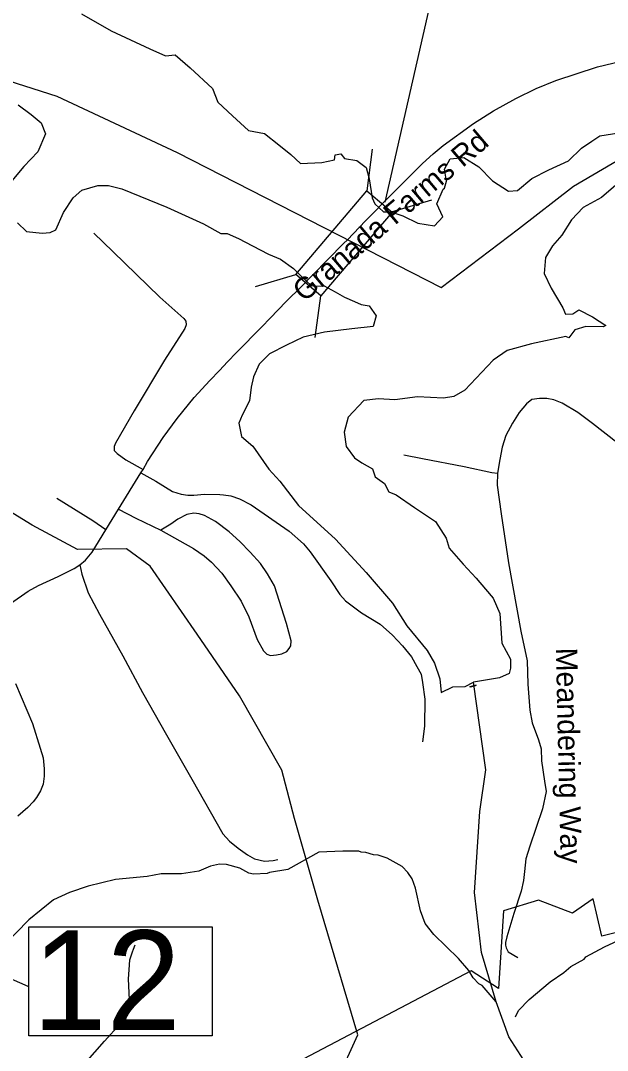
# Model space of a CAD drawing. Extents: x 1159738 to 1321356, y 736314 to 882035.
# Drawn here: x 1283504 to 1285565, y 753698 to 757313 of the extents above; entities that cross this region are included whole.
import ezdxf

# ---------------------------------------------------------------- set-up
doc = ezdxf.new("R2010")
doc.units = 0
for name, color, linetype in [('Exist Boundary Political City Limit New', 7, 'Continuous'), ('Exist Hydrographic Creek Double Shore', 7, 'Continuous'), ('Exist Hydrographic Creek Single Shore', 7, 'Continuous'), ('Exist Hydrographic Lake Dam', 7, 'Continuous'), ('Exist Hydrographic Misc Water Feature', 7, 'Continuous'), ('Exist Road Non-System Type 51', 7, 'Continuous'), ('Exist Road Non-System Type 51 Label', 7, 'Continuous'), ('Exist Road Secondary Structure Standard Bridge CELL', 7, 'Continuous'), ('Exist Road Secondary Structure Standard Bridge Number Label', 7, 'Continuous'), ('Exist Road Secondary Type 51 Attributed', 7, 'Continuous'), ('Exist Road Secondary Type 51 Label', 7, 'Continuous'), ('Exist Utilities Electrical Transmission Line', 7, 'Continuous'), ('Map Preparation Boundary City Limit Buffer Line', 7, 'Continuous')]:
    doc.layers.add(name, color=color, linetype=linetype)

msp = doc.modelspace()

# ---------------------------------------------------------------- linework, layer by layer
at = {"layer": 'Exist Boundary Political City Limit New'}
for points in [[(1280018.1, 757340.6), (1280236.8, 756834.3), (1280495.5, 756917.6), (1280706.6, 756441.3), (1280847.5, 756529.7), (1280868.5, 756454.3), (1280930.2, 756459.6), (1280976.3, 756484.6), (1280986.6, 756728.2), (1280999.3, 756824.5), (1281041.5, 756912.8), (1281181.8, 757003), (1281357.9, 756992.9), (1281622.7, 757052.4), (1281779.5, 757056.2), (1282025.2, 757025.5), (1282305.4, 757144.6), (1283145.9, 757202.8), (1283630.6, 757047.6), (1284053.8, 756850), (1284981.5, 756376.9), (1285252.7, 756582.6), (1285445.9, 756731.6), (1285615.9, 756832.2)], [(1285986.1, 754207.3), (1285545.9, 754099.1), (1285515.2, 754229.7), (1285442.3, 754179.8), (1285323.3, 754225.8), (1285200.5, 754187.4), (1285182.5, 753915.2), (1285086.5, 753976.7), (1283568.2, 753178.6)]]:
    msp.add_lwpolyline(points, dxfattribs=at)
at = {"layer": 'Exist Hydrographic Creek Double Shore'}
for points in [[(1283717.5, 757336.8), (1283822, 757277.9), (1283957.5, 757214.5), (1284013.1, 757190), (1284046.4, 757193.4), (1284099.8, 757147.8), (1284178.2, 757074.7), (1284197.1, 757026.9), (1284248.2, 756979), (1284304.9, 756927.9), (1284360.5, 756916.8), (1284410.5, 756876.7), (1284452.7, 756843.4), (1284487.2, 756812.2), (1284561.6, 756815.6), (1284606.1, 756824.5), (1284608.9, 756842.4)], [(1283495.4, 757017.2), (1283540.9, 756983.9), (1283575.9, 756954.2), (1283590.8, 756915.6), (1283564.5, 756852.6), (1283515.6, 756800.9), (1283472.7, 756751)], [(1284608.9, 756842.4), (1284628.9, 756845.7), (1284642.2, 756829), (1284685.6, 756822.4), (1284717.8, 756797.9), (1284728.9, 756757.9), (1284738.9, 756691.1), (1284747.8, 756670), (1284778.8, 756641.5), (1284804.4, 756641.5), (1284846.6, 756628.2), (1284899.9, 756602.6), (1284957.7, 756592.6), (1284986.6, 756624.8), (1284966.6, 756670.4), (1284988.9, 756721.6), (1284993.3, 756724.9), (1285000, 756749.4), (1284993.3, 756791.7), (1285013.3, 756828.4), (1285061.1, 756832.8), (1285113.3, 756800.6), (1285162.2, 756750.5), (1285217.8, 756714.9), (1285250, 756717.1), (1285299.3, 756759.3), (1285359.3, 756789.3), (1285428.2, 756821.6), (1285474.9, 756866.1), (1285510.5, 756890.5), (1285538.3, 756909.4), (1285634.9, 756923.9)], [(1283492.8, 756603), (1283524.3, 756573.2), (1283579.4, 756567.1), (1283608.2, 756568.9), (1283627.5, 756578.5), (1283654.6, 756639.8), (1283688.7, 756690.6), (1283719.4, 756717.7), (1283775.3, 756734.3), (1283812.6, 756734.2), (1283859, 756722.8), (1284017.3, 756658), (1284145.9, 756600.2), (1284207.6, 756566.3), (1284229.5, 756565.4), (1284268.9, 756548.8), (1284318.7, 756522.5), (1284374.7, 756492.8), (1284416.7, 756476.1), (1284462.2, 756442.9), (1284494.6, 756411.3), (1284508.6, 756398.2), (1284524.1, 756383.6)], [(1285594.6, 756735.6), (1285544.6, 756692.2), (1285480.3, 756657.2), (1285439.2, 756613.8), (1285405.8, 756560.4), (1285372.5, 756522.6), (1285348.1, 756481.4), (1285343.6, 756425.8), (1285368.1, 756373.6), (1285409.2, 756305.4), (1285418.1, 756283.2), (1285443.7, 756284.3), (1285464.8, 756297.6), (1285512.6, 756273.2), (1285560.4, 756243.1), (1285550.4, 756238.7), (1285489.2, 756239.8), (1285451.4, 756227.6), (1285430.3, 756199.8), (1285419.2, 756204.2), (1285299.2, 756178.6), (1285213.6, 756155.3), (1285163.6, 756120.8), (1285064.7, 756016.2), (1285026.4, 755993.1), (1284989.7, 755987.6), (1284898.6, 755992), (1284818.5, 755982), (1284760.8, 755985.3), (1284709.6, 755979.8), (1284654.1, 755920.8), (1284640.7, 755868.6), (1284647.4, 755818.5), (1284676.3, 755778.5), (1284703, 755760.7), (1284739.6, 755739.2), (1284749.6, 755711.4), (1284781.8, 755688.1), (1284797.4, 755659.2), (1284822.9, 755648), (1284887.4, 755603.5), (1284961.9, 755554.6)], [(1284524.1, 756383.6), (1284540.7, 756380.9), (1284570.5, 756381.8), (1284608.9, 756361.7), (1284641.3, 756342.4), (1284677.2, 756327.5), (1284699.9, 756316.1), (1284728.8, 756311.8), (1284752.4, 756276.8), (1284741.9, 756239.1), (1284667.6, 756231.2), (1284571.3, 756219), (1284497, 756201.5), (1284437.5, 756174.3), (1284378.1, 756143.1), (1284342.2, 756107.2), (1284322.1, 756062.6), (1284313.4, 756026.7), (1284308.1, 755978.5), (1284281.9, 755928.1), (1284270.5, 755900.1), (1284280.2, 755853.7), (1284319.5, 755818.7), (1284376.4, 755739), (1284414.7, 755696), (1284480.3, 755611.1), (1284609.8, 755492.9), (1284717.4, 755375.6), (1284810.8, 755268.3), (1284860.6, 755188.7), (1284932.4, 755102), (1284957.6, 755056.8), (1284976.8, 755002.5), (1284981.2, 754954.4), (1285022.3, 754974.5), (1285066.1, 754975.4), (1285094.9, 754991.1)], [(1284961.9, 755554.6), (1284998.5, 755495.7), (1285009.6, 755461.2), (1285058.5, 755404.5), (1285104.1, 755355.5), (1285137.4, 755316.6), (1285163.9, 755285.9), (1285187.3, 755231.4), (1285193.9, 755128), (1285225.1, 755071.3), (1285225.1, 755040.2), (1285220.6, 755021.3), (1285186.2, 755006.1), (1285094.9, 754991.1)]]:
    msp.add_lwpolyline(points, dxfattribs=at)
at = {"layer": 'Exist Hydrographic Creek Single Shore'}
for points in [[(1285174, 753868.3), (1285122.8, 754041.6), (1285098.9, 754252.2), (1285117.5, 754536), (1285138.8, 754682.7), (1285094.9, 754991.1)], [(1284849.9, 752471.5), (1284997.7, 752504.4), (1285108.6, 752555.7), (1285198.9, 752633.8), (1285266.6, 752713.9), (1285322.8, 752865.6), (1285332.3, 752962.4), (1285363.1, 753135), (1285369.3, 753272.6), (1285379, 753376.3), (1285336.8, 753559), (1285282.7, 753647), (1285218.8, 753745.6), (1285174, 753868.3)]]:
    msp.add_lwpolyline(points, dxfattribs=at)
at = {"layer": 'Exist Hydrographic Lake Dam'}
for points in [[(1285082.1, 754973.9), (1285104, 754979.7), (1285103.9, 754979.9), (1285082, 754974.2)], [(1285083.9, 754974.4), (1285102.2, 754979.2), (1285102.3, 754978.7), (1285084, 754973.9)]]:
    msp.add_lwpolyline(points, close=True, dxfattribs=at)
at = {"layer": 'Exist Hydrographic Misc Water Feature'}
for points in [[(1285174, 753868.3), (1285125.2, 753925.1), (1285113.4, 753931.5), (1285093.9, 753952), (1285078.6, 753978.5), (1285042.5, 754019.9), (1284955, 754104.6), (1284925.3, 754142.8), (1284908.4, 754187.3), (1284890.7, 754267.8), (1284879.5, 754300.1), (1284864.1, 754322.5), (1284844.8, 754343.1), (1284791.6, 754372.6), (1284759.9, 754383.5), (1284743.9, 754383.9), (1284716.1, 754392.8), (1284700.1, 754393.2), (1284692.2, 754397.4), (1284635.5, 754396.7), (1284552.1, 754393.4), (1284442.4, 754332.6), (1284378.1, 754322.4), (1284370, 754318.7), (1284321.9, 754316.1), (1284306, 754320.5), (1284274.4, 754337.4), (1284226.8, 754350.8), (1284202.9, 754351.4), (1284170.7, 754344.4), (1284130.2, 754327.6), (1284069.4, 754317.8), (1283997.8, 754317.4), (1283948.4, 754308), (1283837.2, 754298), (1283740.6, 754274.8), (1283676, 754252.6), (1283619.2, 754226.2), (1283532.3, 754155.9), (1283397.4, 754018.6)], [(1285242.3, 753816.1), (1285252.8, 753837.5), (1285289.9, 753876.4), (1285363.7, 753938.3), (1285412.6, 753970.9), (1285437.2, 753992.1), (1285483.6, 754018.3), (1285490.1, 754026.6), (1285555.1, 754060.8), (1285668.6, 754113.5)]]:
    msp.add_lwpolyline(points, dxfattribs=at)
at = {"layer": 'Exist Road Non-System Type 51'}
for points in [[(1283761.5, 756566.9), (1283828.1, 756502.2), (1283992.8, 756342.4), (1284077.4, 756267.9), (1284083.7, 756258.4), (1284085.6, 756245.2), (1284081.2, 756232.7), (1284008.9, 756121.3), (1283902.8, 755943.8), (1283836.9, 755829.7), (1283832.5, 755818.4), (1283832.5, 755803.9), (1283842.5, 755793.8), (1283873.9, 755771.8), (1283934.3, 755737.1)], [(1285935.7, 755452.4), (1285888.5, 755486.7), (1285860, 755512.6), (1285818.1, 755568.8), (1285767.2, 755649.2), (1285739.6, 755691.1), (1285697.6, 755744.7), (1285598.9, 755831.7), (1285513.3, 755898.6), (1285461.5, 755937.9), (1285406.2, 755970.1), (1285377.1, 755982.5), (1285353, 755987), (1285327.1, 755987), (1285300.3, 755983.4), (1285281.6, 755968.2), (1285255.7, 755937.9), (1285231.6, 755899.5), (1285208.5, 755856.6), (1285196, 755815.6), (1285187, 755772.7), (1285178.8, 755724.7)], [(1284850, 755788.7), (1284915.9, 755775.4), (1285061.6, 755747.5), (1285159.1, 755726.6), (1285178.8, 755724.7)], [(1283926.3, 755725.4), (1283979.2, 755696.5), (1284038, 755660.4), (1284068.3, 755650.6), (1284091, 755647.5), (1284112.8, 755647), (1284150.2, 755650.6), (1284204.1, 755649.7), (1284217, 755648.4), (1284242.4, 755644.4), (1284273.1, 755634.6), (1284313.6, 755613.2), (1284446.9, 755521), (1284498.2, 755476.4), (1284521.6, 755448.6), (1284594.2, 755347), (1284625.4, 755298.9), (1284644.8, 755275.9), (1284701.8, 755234), (1284766.8, 755194.8), (1284810.7, 755155.1), (1284845.5, 755118.1), (1284877.5, 755079.7), (1284896.2, 755045.9), (1284910.5, 755018.7), (1284915.4, 754989.7), (1284924.2, 754931.2)], [(1285178.8, 755724.7), (1285178.2, 755682.9), (1285192.5, 755582.1), (1285218.4, 755409.8), (1285261.2, 755170.2), (1285283.4, 755066.1), (1285286.1, 754983.1), (1285293.3, 754892.1), (1285301.3, 754848.3), (1285322.7, 754787.6), (1285332.5, 754756.2), (1285334.2, 754714.2), (1285344.1, 754642.8), (1285350.3, 754607.1), (1285337.8, 754545.5), (1285293.2, 754415.2), (1285279, 754370.1), (1285274.5, 754326.4), (1285270, 754294.2), (1285262.9, 754256.7), (1285236.1, 754178.2), (1285212.1, 754096.9), (1285206.8, 754076.1), (1285206.8, 754067.2), (1285209.5, 754058.3), (1285216.6, 754044), (1285250.5, 754023.5)], [(1283803.7, 755525.4), (1283757.7, 755556.7), (1283631.6, 755635.3)], [(1283847.8, 755598.4), (1283908.1, 755566.5), (1283996.7, 755524.6)], [(1283996.7, 755524.6), (1284111.6, 755460.4), (1284148.8, 755434.3), (1284174.7, 755412.1), (1284211.2, 755372.8), (1284242.8, 755328.7), (1284278.8, 755274.5), (1284305.9, 755220.6), (1284335.2, 755141), (1284357, 755100.3), (1284368.6, 755089.1), (1284381.9, 755084.7), (1284402.9, 755086.5), (1284421.1, 755090), (1284438.9, 755098), (1284447.8, 755108.3), (1284453.2, 755118.5), (1284454.5, 755135.9), (1284438.5, 755197), (1284395.7, 755328.5), (1284371.7, 755371.2), (1284346.7, 755407.3), (1284310.7, 755447.3), (1284273.8, 755485.1), (1284236.8, 755519), (1284188.7, 755554.2), (1284150.1, 755575.9), (1284131.4, 755582.1), (1284111.8, 755583.5), (1284087.8, 755579), (1284056.1, 755562.5), (1284031.7, 755545.1), (1283996.7, 755524.6)], [(1283711.9, 755402.4), (1283718.4, 755370.3), (1283741.4, 755303.8), (1283780.7, 755229.4), (1283862.9, 755083.5), (1283932.1, 754954.6), (1284016.5, 754806), (1284105.3, 754649.6), (1284214.6, 754458.1), (1284237.5, 754432), (1284268.4, 754407.4), (1284300.9, 754384.8), (1284326, 754370.2), (1284361.1, 754361.8), (1284391.1, 754364.8), (1284407, 754368.1)], [(1283485.6, 754986), (1283545.5, 754845.4), (1283572.2, 754759.4), (1283582.5, 754725.1), (1283586.6, 754686.7), (1283587, 754660.7), (1283582.9, 754632.2), (1283573.8, 754608.9), (1283560.2, 754585.3), (1283548.2, 754570), (1283529.7, 754551), (1283494.2, 754519.6)], [(1284924.2, 754931.2), (1284923.3, 754835.9), (1284916.2, 754781.5)], [(1283884, 753849), (1283886.6, 753875.5), (1283882.5, 753949), (1283884.6, 753981.2), (1283888, 754015.5), (1283896.9, 754043.4), (1283900.3, 754053.7), (1283905.8, 754068.8)], [(1283309, 753159.6), (1283331.5, 753180.2), (1283354.8, 753214.5), (1283378.8, 753255.7), (1283423.4, 753337.6), (1283453.6, 753382.3), (1283479.6, 753414.5), (1283514.6, 753444), (1283540, 753460.5), (1283600.9, 753503.6), (1283627.7, 753528.3), (1283648.9, 753555), (1283705.2, 753623.7), (1283798.3, 753729.6), (1283853.1, 753790.7), (1283868.2, 753814.7), (1283879.2, 753838.7), (1283884, 753849)]]:
    msp.add_lwpolyline(points, dxfattribs=at)
at = {"layer": 'Exist Road Secondary Structure Standard Bridge CELL'}
for p, q in [((1284720.9, 756715.2), (1284740.6, 756861.8)), ((1284807.1, 756641.8), (1284948.6, 756684.6)), ((1284329.2, 756379.5), (1284470.8, 756422.3)), ((1284539.2, 756200.7), (1284558.9, 756347.3))]:
    msp.add_line(p, q, dxfattribs=at)
msp.add_lwpolyline([(1284470.8, 756422.3), (1284720.5, 756715.6), (1284808.6, 756640.5), (1284558.9, 756347.3)], close=True, dxfattribs=at)
at = {"layer": 'Exist Road Secondary Structure Standard Bridge Number Label'}
for p, q in [((1284784.5, 756675.6), (1285361.2, 759198.5)), ((1281391.7, 754859.8), (1283528.6, 753923.7))]:
    msp.add_line(p, q, dxfattribs=at)
msp.add_lwpolyline([(1283533.2, 754131.6), (1284177.3, 754131.6), (1284177.3, 753749.2), (1283533.2, 753749.2)], close=True, dxfattribs=at)
at = {"layer": 'Exist Road Secondary Type 51 Attributed'}
for points in [[(1284651.9, 756544.1), (1284715.3, 756610.7), (1284808.9, 756705.5), (1284881.6, 756778.3), (1284916.2, 756812.2), (1284953.3, 756845.6), (1284987.8, 756875.1), (1285095.1, 756952.2), (1285165.4, 756996.8), (1285243.4, 757040.2), (1285315.4, 757075.2), (1285383.9, 757103.5), (1285530.2, 757151.2), (1285613.8, 757171.4)], [(1283468.7, 755266.8), (1283530.5, 755310.7), (1283567.1, 755330.2), (1283635.6, 755361.9), (1283692.4, 755389.9), (1283711.9, 755402.4), (1283731.9, 755419.5), (1283754.9, 755446.7), (1283803.7, 755525.4), (1283847.8, 755598.4), (1283926.3, 755725.4), (1283934.3, 755737.1), (1283950.1, 755765.5), (1284004.7, 755849.8), (1284054.3, 755916.5), (1284113.2, 755989.8), (1284168.5, 756049.5), (1284203.1, 756084.7), (1284230.7, 756114.9), (1284262.6, 756148.2), (1284351.3, 756238.5), (1284380, 756268.5), (1284437.2, 756326.9), (1284490.6, 756379.8), (1284530.7, 756421), (1284638.1, 756530.5), (1284651.8, 756544.1), (1284651.9, 756544.1)]]:
    msp.add_lwpolyline(points, dxfattribs=at)
at = {"layer": 'Exist Utilities Electrical Transmission Line'}
for points in [[(1284421, 754681.5), (1284272.9, 754942.1), (1284123.7, 755158.6), (1283958.9, 755398.1), (1283875.3, 755458.8), (1283703.2, 755456.6), (1283544.4, 755541.3), (1282897.7, 755938.8), (1282689, 756057.4)], [(1284616.8, 753596.1), (1284688.5, 753751.9), (1284547.9, 754225.6), (1284465.9, 754511.9), (1284421, 754681.5)]]:
    msp.add_lwpolyline(points, dxfattribs=at)
at = {"layer": 'Map Preparation Boundary City Limit Buffer Line'}
for points in [[(1280018.1, 757340.6), (1280236.8, 756834.3), (1280495.5, 756917.6), (1280706.6, 756441.3), (1280847.5, 756529.7), (1280868.5, 756454.3), (1280930.2, 756459.6), (1280976.3, 756484.6), (1280986.6, 756728.2), (1280999.3, 756824.5), (1281041.5, 756912.8), (1281181.8, 757003), (1281357.9, 756992.9), (1281622.7, 757052.4), (1281779.5, 757056.2), (1282025.2, 757025.5), (1282305.4, 757144.6), (1283145.9, 757202.8), (1283630.6, 757047.6), (1284053.8, 756850), (1284981.5, 756376.9), (1285252.7, 756582.6), (1285445.9, 756731.6), (1285615.9, 756832.2)], [(1285986.1, 754207.3), (1285545.9, 754099.1), (1285515.2, 754229.7), (1285442.3, 754179.8), (1285323.3, 754225.8), (1285200.5, 754187.4), (1285182.5, 753915.2), (1285086.5, 753976.7), (1283568.2, 753178.6)]]:
    msp.add_lwpolyline(points, dxfattribs=at)

# ---------------------------------------------------------------- texts
at = {"layer": 'Exist Road Non-System Type 51 Label'}
msp.add_text('Meandering Way', height=75, rotation=271.2833, dxfattribs=at).set_placement((1285384.2, 755110.8))
at = {"layer": 'Exist Road Secondary Structure Standard Bridge Number Label'}
msp.add_text('12', height=350, dxfattribs=at).set_placement((1283545.7, 753769))
at = {"layer": 'Exist Road Secondary Type 51 Label'}
msp.add_text('Granada Farms Rd', height=75, rotation=40.3245, dxfattribs=at).set_placement((1284499.9, 756322.8))

doc.saveas('drawing.dxf')
